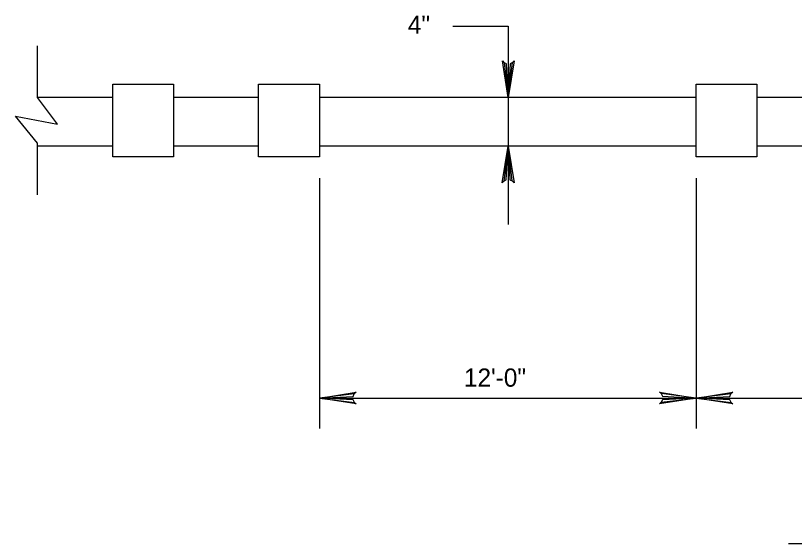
# Model space of a CAD drawing. Extents: x 632008 to 634206, y 294231 to 297795.
# Drawn here: x 632298.7 to 632427, y 296238.5 to 296325.5 of the extents above; entities that cross this region are included whole.
import ezdxf

# ---------------------------------------------------------------- set-up
doc = ezdxf.new("R2010")
doc.units = 0
for name, color, linetype in [('1', 7, 'Continuous'), ('Level 1', 7, 'Continuous'), ('Level 2', 7, 'Continuous')]:
    doc.layers.add(name, color=color, linetype=linetype)

msp = doc.modelspace()

# ---------------------------------------------------------------- linework, layer by layer
at = {"layer": '1'}
msp.add_line((632425.96, 296238.55), (632521.83, 296238.55), dxfattribs=at)
at = {"layer": 'Level 1'}
for p, q in [((632314.72, 296311.98), (632302.33, 296311.98)), ((632338.73, 296311.98), (632324.72, 296311.98)), ((632410.77, 296311.98), (632348.74, 296311.98)), ((632434.78, 296311.98), (632420.77, 296311.98)), ((632314.72, 296303.98), (632302.32, 296303.98)), ((632338.73, 296303.98), (632324.72, 296303.98)), ((632410.77, 296303.98), (632348.74, 296303.98)), ((632434.78, 296303.98), (632420.77, 296303.98))]:
    msp.add_line(p, q, dxfattribs=at)
at = {"layer": 'Level 2'}
for p, q in [((632370.69, 296323.73), (632379.83, 296323.73)), ((632379.83, 296323.73), (632379.83, 296291.09)), ((632302.33, 296311.98), (632302.33, 296320.48)), ((632305.62, 296307.59), (632302.33, 296311.98)), ((632302.32, 296304.46), (632298.71, 296308.93)), ((632298.71, 296308.93), (632305.62, 296307.59)), ((632302.33, 296295.97), (632302.32, 296304.46)), ((632348.74, 296298.73), (632348.74, 296257.49)), ((632410.77, 296298.73), (632410.77, 296257.49)), ((632348.74, 296262.49), (632410.77, 296262.49)), ((632410.77, 296262.49), (632516.82, 296262.49))]:
    msp.add_line(p, q, dxfattribs=at)
for points in [[(632380.55, 296317.74), (632380.13, 296317.53), (632379.83, 296311.98), (632380.55, 296317.74), (632380.8, 296318.03), (632379.83, 296311.98), (632379.55, 296317.52), (632379.14, 296317.72), (632379.83, 296311.98), (632378.86, 296318.03), (632379.14, 296317.72)], [(632379.1, 296298.23), (632379.51, 296298.44), (632379.82, 296303.98), (632379.1, 296298.23), (632378.85, 296297.93), (632379.82, 296303.98), (632380.1, 296298.45), (632380.5, 296298.24), (632379.82, 296303.98), (632380.78, 296297.93), (632380.5, 296298.24)], [(632354.49, 296261.77), (632354.28, 296262.19), (632348.74, 296262.49), (632354.49, 296261.77), (632354.78, 296261.52), (632348.74, 296262.49), (632354.27, 296262.77), (632354.47, 296263.18), (632348.74, 296262.49), (632354.78, 296263.45), (632354.47, 296263.18)], [(632405.01, 296263.22), (632405.22, 296262.8), (632410.77, 296262.49), (632405.01, 296263.22), (632404.72, 296263.47), (632410.77, 296262.49), (632405.23, 296262.22), (632405.03, 296261.81), (632410.77, 296262.49), (632404.72, 296261.53), (632405.03, 296261.81)], [(632416.52, 296261.77), (632416.31, 296262.19), (632410.77, 296262.49), (632416.52, 296261.77), (632416.81, 296261.52), (632410.77, 296262.49), (632416.3, 296262.77), (632416.5, 296263.18), (632410.77, 296262.49), (632416.81, 296263.45), (632416.5, 296263.18)]]:
    msp.add_lwpolyline(points, dxfattribs=at)
for points in [[(632314.72, 296314.2), (632324.72, 296314.2), (632324.72, 296302.2), (632314.72, 296302.2)], [(632338.73, 296314.2), (632348.74, 296314.2), (632348.74, 296302.2), (632338.73, 296302.2)], [(632410.77, 296314.2), (632420.77, 296314.2), (632420.77, 296302.2), (632410.77, 296302.2)]]:
    msp.add_lwpolyline(points, close=True, dxfattribs=at)

# ---------------------------------------------------------------- texts
msp.add_text('4"', height=3, rotation=360, dxfattribs=at).set_placement((632363.3, 296322.48))
msp.add_text('12\'-0"', height=3, dxfattribs=at).set_placement((632372.54, 296264.36))

doc.saveas('drawing.dxf')
